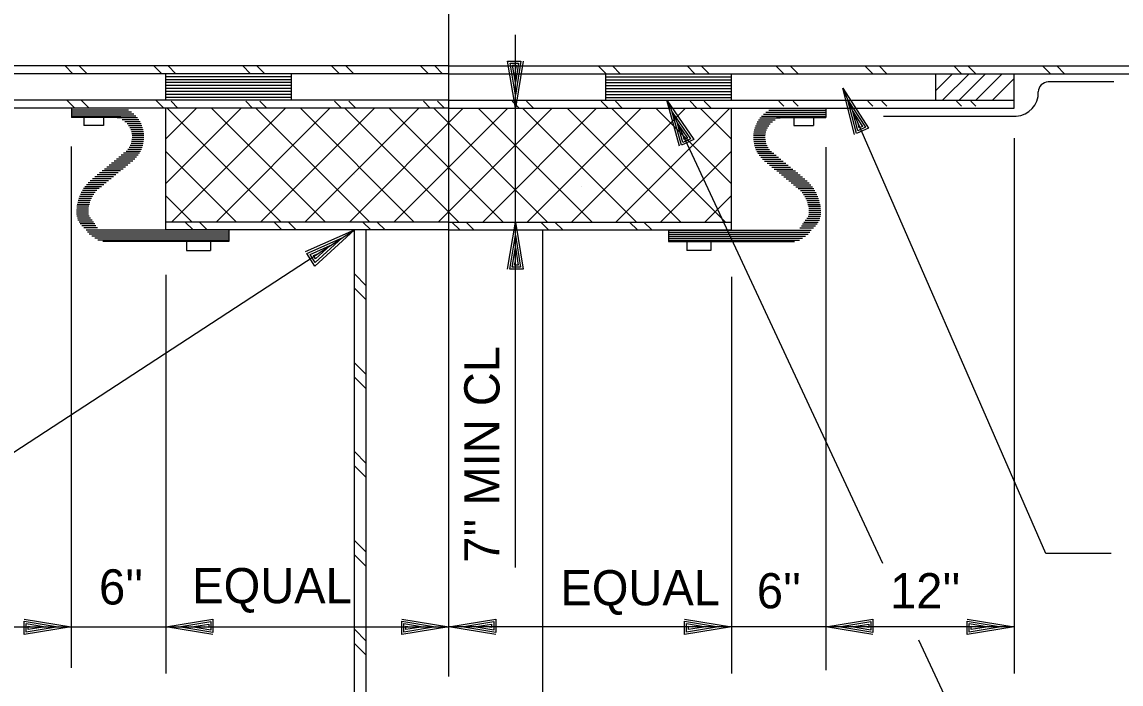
# Model space of a CAD drawing. Extents: x 22422.9 to 22498.9, y 22369.6 to 22415.
# Drawn here: x 22465.87 to 22471.7, y 22384.56 to 22388.07 of the extents above; entities that cross this region are included whole.
import ezdxf

# ---------------------------------------------------------------- set-up
doc = ezdxf.new("R2010")
doc.units = 0
for name, color, linetype in [('Level 1', 7, 'Continuous'), ('Level 10', 7, 'Continuous'), ('Level 2', 7, 'Continuous'), ('Level 4', 7, 'Continuous'), ('Level 7', 7, 'Continuous'), ('Level 8', 7, 'Continuous')]:
    doc.layers.add(name, color=color, linetype=linetype)

msp = doc.modelspace()

# ---------------------------------------------------------------- linework, layer by layer
at = {"layer": 'Level 1'}
for p, q in [((22468.1298, 22384.5979), (22468.1298, 22394.0328)), ((22468.4836, 22387.613), (22468.4836, 22388.0015)), ((22467.2965, 22387.7797), (22466.6298, 22387.7797)), ((22467.2965, 22387.764), (22466.6298, 22387.764)), ((22468.9631, 22387.7797), (22469.6298, 22387.7797)), ((22468.9631, 22387.764), (22469.6298, 22387.764)), ((22470.7131, 22387.7069), (22470.8015, 22387.7953)), ((22470.7493, 22387.6547), (22470.8899, 22387.7953)), ((22470.8377, 22387.6547), (22470.9783, 22387.7953)), ((22470.9261, 22387.6547), (22471.0667, 22387.7953)), ((22471.0145, 22387.6547), (22471.1298, 22387.77)), ((22467.2965, 22387.7484), (22466.6298, 22387.7484)), ((22467.2965, 22387.7328), (22466.6298, 22387.7328)), ((22467.2965, 22387.7172), (22466.6298, 22387.7172)), ((22467.2965, 22387.7015), (22466.6298, 22387.7015)), ((22468.9631, 22387.7484), (22469.6298, 22387.7484)), ((22468.9631, 22387.7328), (22469.6298, 22387.7328)), ((22468.9631, 22387.7172), (22469.6298, 22387.7172)), ((22468.9631, 22387.7015), (22469.6298, 22387.7015)), ((22468.1298, 22387.6547), (22465.1298, 22387.6547)), ((22467.2965, 22387.6859), (22466.6298, 22387.6859)), ((22467.2965, 22387.6703), (22466.6298, 22387.6703)), ((22468.1298, 22387.6547), (22471.1298, 22387.6547)), ((22468.9631, 22387.6859), (22469.6298, 22387.6859)), ((22468.9631, 22387.6703), (22469.6298, 22387.6703)), ((22468.1298, 22387.613), (22465.1298, 22387.613)), ((22466.6298, 22386.9672), (22466.6298, 22387.613)), ((22468.1298, 22387.613), (22471.1298, 22387.613)), ((22468.4836, 22387.0088), (22468.4836, 22387.613)), ((22469.6298, 22386.9672), (22469.6298, 22387.613)), ((22466.1946, 22387.5633), (22466.1946, 22387.5204)), ((22466.2982, 22387.5633), (22466.2982, 22387.5204)), ((22468.4836, 22387.5713), (22468.4836, 22387.5713)), ((22469.9614, 22387.5633), (22469.9614, 22387.5204)), ((22470.065, 22387.5633), (22470.065, 22387.5204)), ((22470.8989, 22387.5691), (22470.8989, 22387.5691)), ((22466.2982, 22387.5204), (22466.1946, 22387.5204)), ((22469.9614, 22387.5204), (22470.065, 22387.5204)), ((22466.1276, 22387.4098), (22466.1276, 22384.6433)), ((22470.1298, 22387.4065), (22470.1298, 22384.632)), ((22471.1298, 22387.4529), (22471.1298, 22384.6134)), ((22467.6298, 22387.2588), (22467.6298, 22387.2588)), ((22468.4836, 22387.252), (22468.4836, 22387.252)), ((22468.8041, 22387.2588), (22468.8041, 22387.2588)), ((22468.834, 22387.1962), (22468.834, 22387.1962)), ((22468.1298, 22387.0088), (22466.6298, 22387.0088)), ((22468.1298, 22387.0088), (22469.6298, 22387.0088)), ((22468.4836, 22385.1752), (22468.4836, 22387.0088)), ((22468.1298, 22386.9672), (22466.6298, 22386.9672)), ((22468.1298, 22386.9672), (22469.6298, 22386.9672)), ((22468.4836, 22386.9463), (22468.4836, 22386.9463)), ((22466.7386, 22386.9055), (22466.7386, 22386.8578)), ((22466.866, 22386.9055), (22466.866, 22386.8578)), ((22469.3936, 22386.9055), (22469.3936, 22386.8578)), ((22469.521, 22386.9055), (22469.521, 22386.8578)), ((22466.7386, 22386.8578), (22466.866, 22386.8578)), ((22469.521, 22386.8578), (22469.3936, 22386.8578)), ((22466.6298, 22386.7289), (22466.6298, 22384.6134)), ((22469.6298, 22386.7179), (22469.6298, 22384.6134)), ((22465.1298, 22384.8612), (22466.1276, 22384.8612)), ((22466.1276, 22384.8612), (22466.6298, 22384.8612)), ((22466.6298, 22384.8612), (22466.6298, 22384.8612)), ((22466.6298, 22384.8612), (22468.1298, 22384.8612)), ((22466.6991, 22384.8612), (22466.6991, 22384.8612)), ((22468.0605, 22384.8612), (22468.0605, 22384.8612)), ((22469.6298, 22384.8612), (22468.1298, 22384.8612)), ((22468.1298, 22384.8612), (22468.1298, 22384.8612)), ((22468.1298, 22384.8612), (22468.1298, 22384.8612)), ((22468.1991, 22384.8612), (22468.1991, 22384.8612)), ((22469.5605, 22384.8612), (22469.5605, 22384.8612)), ((22469.6298, 22384.8612), (22469.6298, 22384.8612)), ((22470.1298, 22384.8612), (22469.6298, 22384.8612)), ((22471.1298, 22384.8612), (22470.1298, 22384.8612))]:
    msp.add_line(p, q, dxfattribs=at)
at = {"layer": 'Level 10'}
for p, q in [((22464.6557, 22385.0258), (22467.6298, 22386.9672)), ((22467.6298, 22386.9672), (22467.6298, 22386.9672)), ((22467.5645, 22386.9245), (22467.5645, 22386.9245))]:
    msp.add_line(p, q, dxfattribs=at)
msp.add_lwpolyline([(22467.3695, 22386.8528), (22467.6298, 22386.9672), (22467.4203, 22386.7749), (22467.3769, 22386.8415), (22467.5645, 22386.9245), (22467.4222, 22386.794), (22467.3943, 22386.8367), (22467.5017, 22386.8835), (22467.424, 22386.8131), (22467.4126, 22386.8307), (22467.4364, 22386.8409)], dxfattribs=at)
at = {"layer": 'Level 2'}
for p, q in [((22468.1298, 22387.8369), (22461.434, 22387.8369)), ((22468.1298, 22387.8369), (22474.813, 22387.8369)), ((22468.1298, 22387.7953), (22461.4643, 22387.7953)), ((22466.6298, 22387.6547), (22466.6298, 22387.7953)), ((22467.2965, 22387.6547), (22467.2965, 22387.7953)), ((22468.1298, 22387.7953), (22474.7895, 22387.7953)), ((22468.9631, 22387.6547), (22468.9631, 22387.7953)), ((22469.6298, 22387.6547), (22469.6298, 22387.7953)), ((22470.7131, 22387.6547), (22470.7131, 22387.7953)), ((22471.1298, 22387.613), (22471.1298, 22387.7953)), ((22466.1285, 22387.613), (22466.1285, 22387.5633)), ((22470.1311, 22387.613), (22470.1311, 22387.5633)), ((22466.3909, 22387.5633), (22466.1285, 22387.5633)), ((22469.8687, 22387.5633), (22470.1311, 22387.5633)), ((22466.9643, 22386.9672), (22466.9643, 22386.9055)), ((22467.6298, 22383.8568), (22467.6298, 22386.9672)), ((22467.6923, 22383.8568), (22467.6923, 22386.9672)), ((22468.6298, 22383.8568), (22468.6298, 22386.9672)), ((22469.2953, 22386.9672), (22469.2953, 22386.9055)), ((22466.9643, 22386.9055), (22466.2958, 22386.9055)), ((22469.2953, 22386.9055), (22469.9648, 22386.9055))]:
    msp.add_line(p, q, dxfattribs=at)
for points in [[(22468.5249, 22387.8623), (22468.4836, 22387.613), (22468.4422, 22387.8623), (22468.5129, 22387.8623), (22468.4836, 22387.6823), (22468.4556, 22387.8517), (22468.5009, 22387.8517), (22468.4836, 22387.749), (22468.4689, 22387.841), (22468.4876, 22387.841), (22468.4836, 22387.8183)], [(22471.6445, 22385.2506), (22471.297, 22385.2506), (22470.2199, 22387.7191)], [(22470.2818, 22387.474), (22470.2199, 22387.7191), (22470.3575, 22387.5071), (22470.2928, 22387.4788), (22470.2477, 22387.6555), (22470.341, 22387.5115), (22470.2995, 22387.4934), (22470.2743, 22387.5944), (22470.3245, 22387.5159), (22470.3074, 22387.5085), (22470.302, 22387.5309)], [(22469.3548, 22387.4112), (22469.2868, 22387.6547), (22469.4297, 22387.4462), (22469.3657, 22387.4163), (22469.3161, 22387.5918), (22469.4131, 22387.4502), (22469.372, 22387.4311), (22469.3443, 22387.5314), (22469.3965, 22387.4543), (22469.3796, 22387.4464), (22469.3736, 22387.4686)], [(22470.4334, 22385.198), (22469.2868, 22387.6547)], [(22466.4724, 22387.613), (22466.1298, 22387.613)], [(22466.4118, 22387.613), (22466.1298, 22387.613)], [(22466.4323, 22387.6026), (22466.1298, 22387.6026)], [(22466.4476, 22387.5922), (22466.1298, 22387.5922)], [(22466.46, 22387.5817), (22466.1298, 22387.5817)], [(22469.7872, 22387.613), (22470.1298, 22387.613)], [(22469.7996, 22387.5817), (22470.1298, 22387.5817)], [(22469.812, 22387.5922), (22470.1298, 22387.5922)], [(22469.8274, 22387.6026), (22470.1298, 22387.6026)], [(22469.8478, 22387.613), (22470.1298, 22387.613)], [(22466.4703, 22387.5713), (22466.1298, 22387.5713)], [(22466.4789, 22387.5609), (22466.3708, 22387.5609)], [(22466.4863, 22387.5505), (22466.3975, 22387.5505)], [(22466.4926, 22387.5401), (22466.4128, 22387.5401)], [(22466.4978, 22387.5297), (22466.4237, 22387.5297)], [(22469.7618, 22387.5297), (22469.8359, 22387.5297)], [(22469.7671, 22387.5401), (22469.8468, 22387.5401)], [(22469.7733, 22387.5505), (22469.8621, 22387.5505)], [(22469.7807, 22387.5609), (22469.8888, 22387.5609)], [(22469.7893, 22387.5713), (22470.1298, 22387.5713)], [(22466.5023, 22387.5192), (22466.432, 22387.5192)], [(22466.5058, 22387.5088), (22466.4384, 22387.5088)], [(22466.5087, 22387.4984), (22466.4433, 22387.4984)], [(22466.5108, 22387.488), (22466.4469, 22387.488)], [(22466.5123, 22387.4776), (22466.4493, 22387.4776)], [(22466.5131, 22387.4672), (22466.4505, 22387.4672)], [(22469.7465, 22387.4672), (22469.8091, 22387.4672)], [(22469.7473, 22387.4776), (22469.8104, 22387.4776)], [(22469.7488, 22387.488), (22469.8127, 22387.488)], [(22469.7509, 22387.4984), (22469.8163, 22387.4984)], [(22469.7538, 22387.5088), (22469.8212, 22387.5088)], [(22469.7574, 22387.5192), (22469.8276, 22387.5192)], [(22466.504, 22387.4047), (22466.4352, 22387.4047)], [(22466.5072, 22387.4151), (22466.4408, 22387.4151)], [(22466.5098, 22387.4255), (22466.4451, 22387.4255)], [(22466.5116, 22387.4359), (22466.4481, 22387.4359)], [(22466.5128, 22387.4463), (22466.45, 22387.4463)], [(22466.5133, 22387.4567), (22466.4508, 22387.4567)], [(22469.7463, 22387.4567), (22469.8088, 22387.4567)], [(22469.7468, 22387.4463), (22469.8096, 22387.4463)], [(22469.748, 22387.4359), (22469.8115, 22387.4359)], [(22469.7498, 22387.4255), (22469.8145, 22387.4255)], [(22469.7524, 22387.4151), (22469.8188, 22387.4151)], [(22469.7556, 22387.4047), (22469.8244, 22387.4047)], [(22466.4744, 22387.3526), (22466.3803, 22387.3526)], [(22466.4825, 22387.363), (22466.393, 22387.363)], [(22466.4893, 22387.3734), (22466.4058, 22387.3734)], [(22466.4951, 22387.3838), (22466.4182, 22387.3838)], [(22466.5, 22387.3942), (22466.4278, 22387.3942)], [(22469.7597, 22387.3942), (22469.8318, 22387.3942)], [(22469.7645, 22387.3838), (22469.8414, 22387.3838)], [(22469.7703, 22387.3734), (22469.8538, 22387.3734)], [(22469.7772, 22387.363), (22469.8666, 22387.363)], [(22469.7852, 22387.3526), (22469.8793, 22387.3526)], [(22466.4025, 22387.2901), (22466.3037, 22387.2901)], [(22466.4153, 22387.3005), (22466.3165, 22387.3005)], [(22466.4281, 22387.3109), (22466.3292, 22387.3109)], [(22466.4408, 22387.3213), (22466.342, 22387.3213)], [(22466.4536, 22387.3317), (22466.3548, 22387.3317)], [(22466.4649, 22387.3422), (22466.3675, 22387.3422)], [(22469.7947, 22387.3422), (22469.8921, 22387.3422)], [(22469.806, 22387.3317), (22469.9049, 22387.3317)], [(22469.8188, 22387.3213), (22469.9176, 22387.3213)], [(22469.8315, 22387.3109), (22469.9304, 22387.3109)], [(22469.8443, 22387.3005), (22469.9432, 22387.3005)], [(22469.8571, 22387.2901), (22469.9559, 22387.2901)], [(22466.3387, 22387.238), (22466.2399, 22387.238)], [(22466.3515, 22387.2484), (22466.2526, 22387.2484)], [(22466.3642, 22387.2588), (22466.2654, 22387.2588)], [(22466.377, 22387.2692), (22466.2782, 22387.2692)], [(22466.3898, 22387.2797), (22466.2909, 22387.2797)], [(22469.8698, 22387.2797), (22469.9687, 22387.2797)], [(22469.8826, 22387.2692), (22469.9815, 22387.2692)], [(22469.8954, 22387.2588), (22469.9942, 22387.2588)], [(22469.9081, 22387.2484), (22470.007, 22387.2484)], [(22469.9209, 22387.238), (22470.0197, 22387.238)], [(22466.2643, 22387.1755), (22466.1868, 22387.1755)], [(22466.2751, 22387.1859), (22466.1932, 22387.1859)], [(22466.2877, 22387.1963), (22466.2004, 22387.1963)], [(22466.3004, 22387.2067), (22466.2085, 22387.2067)], [(22466.3132, 22387.2172), (22466.2176, 22387.2172)], [(22466.3259, 22387.2276), (22466.228, 22387.2276)], [(22469.9337, 22387.2276), (22470.0316, 22387.2276)], [(22469.9464, 22387.2172), (22470.042, 22387.2172)], [(22469.9592, 22387.2067), (22470.0511, 22387.2067)], [(22469.972, 22387.1963), (22470.0592, 22387.1963)], [(22469.9845, 22387.1859), (22470.0664, 22387.1859)], [(22469.9953, 22387.1755), (22470.0728, 22387.1755)], [(22466.2269, 22387.113), (22466.1621, 22387.113)], [(22466.2307, 22387.1234), (22466.1648, 22387.1234)], [(22466.2354, 22387.1338), (22466.168, 22387.1338)], [(22466.2409, 22387.1442), (22466.1718, 22387.1442)], [(22466.2475, 22387.1547), (22466.1761, 22387.1547)], [(22466.2552, 22387.1651), (22466.1811, 22387.1651)], [(22470.0044, 22387.1651), (22470.0785, 22387.1651)], [(22470.0121, 22387.1547), (22470.0835, 22387.1547)], [(22470.0187, 22387.1442), (22470.0878, 22387.1442)], [(22470.0242, 22387.1338), (22470.0916, 22387.1338)], [(22470.0289, 22387.1234), (22470.0949, 22387.1234)], [(22470.0327, 22387.113), (22470.0975, 22387.113)], [(22466.2185, 22387.0609), (22466.156, 22387.0609)], [(22466.2189, 22387.0713), (22466.1563, 22387.0713)], [(22466.2199, 22387.0817), (22466.157, 22387.0817)], [(22466.2215, 22387.0922), (22466.1582, 22387.0922)], [(22466.2239, 22387.1026), (22466.1599, 22387.1026)], [(22470.0357, 22387.1026), (22470.0997, 22387.1026)], [(22470.0381, 22387.0922), (22470.1014, 22387.0922)], [(22470.0398, 22387.0817), (22470.1026, 22387.0817)], [(22470.0407, 22387.0713), (22470.1033, 22387.0713)], [(22470.0411, 22387.0609), (22470.1036, 22387.0609)], [(22466.2189, 22387.0505), (22466.1563, 22387.0505)], [(22466.222, 22387.0401), (22466.157, 22387.0401)], [(22466.2292, 22387.0297), (22466.1608, 22387.0297)], [(22466.2389, 22387.0192), (22466.1634, 22387.0192)], [(22466.246, 22387.0088), (22466.1692, 22387.0088)], [(22466.2524, 22386.9984), (22466.1757, 22386.9984)], [(22468.4422, 22386.7595), (22468.4836, 22387.0088), (22468.5249, 22386.7595), (22468.4542, 22386.7595), (22468.4836, 22386.9395), (22468.5116, 22386.7702), (22468.4662, 22386.7702), (22468.4836, 22386.8728), (22468.4982, 22386.7808), (22468.4796, 22386.7808), (22468.4836, 22386.8035)], [(22470.0072, 22386.9984), (22470.084, 22386.9984)], [(22470.0137, 22387.0088), (22470.0904, 22387.0088)], [(22470.0207, 22387.0192), (22470.0962, 22387.0192)], [(22470.0304, 22387.0297), (22470.0988, 22387.0297)], [(22470.0376, 22387.0401), (22470.1026, 22387.0401)], [(22470.0407, 22387.0505), (22470.1033, 22387.0505)], [(22466.2582, 22386.988), (22466.1847, 22386.988)], [(22466.2672, 22386.9776), (22466.195, 22386.9776)], [(22466.9631, 22386.965), (22466.2073, 22386.965)], [(22466.9631, 22386.9545), (22466.2137, 22386.9545)], [(22466.9631, 22386.9441), (22466.2223, 22386.9441)], [(22469.2965, 22386.965), (22470.0524, 22386.965)], [(22469.2965, 22386.9545), (22470.0459, 22386.9545)], [(22469.2965, 22386.9441), (22470.0373, 22386.9441)], [(22469.9924, 22386.9776), (22470.0646, 22386.9776)], [(22470.0014, 22386.988), (22470.0749, 22386.988)], [(22466.9631, 22386.9337), (22466.2375, 22386.9337)], [(22466.9631, 22386.9233), (22466.2533, 22386.9233)], [(22466.9631, 22386.9129), (22466.2686, 22386.9129)], [(22469.2965, 22386.9337), (22470.0221, 22386.9337)], [(22469.2965, 22386.9233), (22470.0063, 22386.9233)], [(22469.2965, 22386.9129), (22469.991, 22386.9129)], [(22465.8782, 22384.9025), (22466.1276, 22384.8612), (22465.8782, 22384.8199), (22465.8782, 22384.8905), (22466.0582, 22384.8612), (22465.8889, 22384.8332), (22465.8889, 22384.8785), (22465.9916, 22384.8612), (22465.8996, 22384.8465), (22465.8996, 22384.8652), (22465.9222, 22384.8612)], [(22466.8791, 22384.8199), (22466.6298, 22384.8612), (22466.8791, 22384.9025), (22466.8791, 22384.8319), (22466.6991, 22384.8612), (22466.8685, 22384.8892), (22466.8685, 22384.8439), (22466.7658, 22384.8612), (22466.8578, 22384.8759), (22466.8578, 22384.8572), (22466.8351, 22384.8612)], [(22467.8805, 22384.9025), (22468.1298, 22384.8612), (22467.8805, 22384.8199), (22467.8805, 22384.8905), (22468.0605, 22384.8612), (22467.8911, 22384.8332), (22467.8911, 22384.8785), (22467.9938, 22384.8612), (22467.9018, 22384.8465), (22467.9018, 22384.8652), (22467.9245, 22384.8612)], [(22468.3791, 22384.8199), (22468.1298, 22384.8612), (22468.3791, 22384.9025), (22468.3791, 22384.8319), (22468.1991, 22384.8612), (22468.3685, 22384.8892), (22468.3685, 22384.8439), (22468.2658, 22384.8612), (22468.3578, 22384.8759), (22468.3578, 22384.8572), (22468.3351, 22384.8612)], [(22469.3805, 22384.9025), (22469.6298, 22384.8612), (22469.3805, 22384.8199), (22469.3805, 22384.8905), (22469.5605, 22384.8612), (22469.3911, 22384.8332), (22469.3911, 22384.8785), (22469.4938, 22384.8612), (22469.4018, 22384.8465), (22469.4018, 22384.8652), (22469.4245, 22384.8612)], [(22470.3791, 22384.8199), (22470.1298, 22384.8612), (22470.3791, 22384.9025), (22470.3791, 22384.8319), (22470.1991, 22384.8612), (22470.3685, 22384.8892), (22470.3685, 22384.8439), (22470.2658, 22384.8612), (22470.3578, 22384.8759), (22470.3578, 22384.8572), (22470.3351, 22384.8612)], [(22470.8805, 22384.9025), (22471.1298, 22384.8612), (22470.8805, 22384.8199), (22470.8805, 22384.8905), (22471.0605, 22384.8612), (22470.8911, 22384.8332), (22470.8911, 22384.8785), (22470.9938, 22384.8612), (22470.9018, 22384.8465), (22470.9018, 22384.8652), (22470.9245, 22384.8612)], [(22471.4047, 22383.8349), (22471.0696, 22383.8349), (22470.6237, 22384.7903)]]:
    msp.add_lwpolyline(points, dxfattribs=at)
at = {"layer": 'Level 7'}
for p, q in [((22471.3103, 22387.7536), (22471.6575, 22387.7536)), ((22470.4365, 22387.5713), (22471.1402, 22387.5713))]:
    msp.add_line(p, q, dxfattribs=at)
for centre, radius, start, end in [((22471.135, 22387.6937), 0.1225, 272.43665, 2.43665), ((22471.3103, 22387.6989), 0.0529, 90, 180)]:
    msp.add_arc(centre, radius, start, end, dxfattribs=at)
at = {"layer": 'Level 8'}
for p, q in [((22470.2199, 22387.7191), (22470.2199, 22387.7191)), ((22468.4836, 22387.6823), (22468.4836, 22387.6823)), ((22469.2868, 22387.6547), (22469.2868, 22387.6547)), ((22470.2477, 22387.6555), (22470.2477, 22387.6555)), ((22468.4836, 22387.613), (22468.4836, 22387.613)), ((22469.3161, 22387.5918), (22469.3161, 22387.5918)), ((22468.4836, 22387.0088), (22468.4836, 22387.0088)), ((22468.4836, 22386.9395), (22468.4836, 22386.9395)), ((22466.0582, 22384.8612), (22466.0582, 22384.8612)), ((22466.1276, 22384.8612), (22466.1276, 22384.8612)), ((22466.6298, 22384.8612), (22466.6298, 22384.8612)), ((22466.6991, 22384.8612), (22466.6991, 22384.8612)), ((22468.0605, 22384.8612), (22468.0605, 22384.8612)), ((22468.1298, 22384.8612), (22468.1298, 22384.8612)), ((22468.1298, 22384.8612), (22468.1298, 22384.8612)), ((22468.1991, 22384.8612), (22468.1991, 22384.8612)), ((22469.5605, 22384.8612), (22469.5605, 22384.8612)), ((22469.6298, 22384.8612), (22469.6298, 22384.8612)), ((22470.1298, 22384.8612), (22470.1298, 22384.8612)), ((22470.1991, 22384.8612), (22470.1991, 22384.8612)), ((22471.0605, 22384.8612), (22471.0605, 22384.8612)), ((22471.1298, 22384.8612), (22471.1298, 22384.8612))]:
    msp.add_line(p, q, dxfattribs=at)
for points in [[(22466.1364, 22387.7953), (22466.0947, 22387.8369)], [(22466.2118, 22387.7953), (22466.1702, 22387.8369)], [(22466.6078, 22387.7953), (22466.5662, 22387.8369)], [(22466.6832, 22387.7953), (22466.6416, 22387.8369)], [(22467.0792, 22387.7953), (22467.0376, 22387.8369)], [(22467.1546, 22387.7953), (22467.113, 22387.8369)], [(22467.5506, 22387.7953), (22467.509, 22387.8369)], [(22467.626, 22387.7953), (22467.5844, 22387.8369)], [(22468.022, 22387.7953), (22467.9804, 22387.8369)], [(22468.0975, 22387.7953), (22468.0558, 22387.8369)], [(22468.9648, 22387.7953), (22468.9232, 22387.8369)], [(22469.0403, 22387.7953), (22468.9986, 22387.8369)], [(22469.4362, 22387.7953), (22469.3946, 22387.8369)], [(22469.5117, 22387.7953), (22469.47, 22387.8369)], [(22469.9076, 22387.7953), (22469.866, 22387.8369)], [(22469.9831, 22387.7953), (22469.9414, 22387.8369)], [(22470.379, 22387.7953), (22470.3374, 22387.8369)], [(22470.4545, 22387.7953), (22470.4128, 22387.8369)], [(22470.8505, 22387.7953), (22470.8088, 22387.8369)], [(22470.9259, 22387.7953), (22470.8842, 22387.8369)], [(22471.3219, 22387.7953), (22471.2802, 22387.8369)], [(22471.3973, 22387.7953), (22471.3556, 22387.8369)], [(22466.1468, 22387.613), (22466.1052, 22387.6547)], [(22466.2223, 22387.613), (22466.1806, 22387.6547)], [(22466.6182, 22387.613), (22466.5766, 22387.6547)], [(22466.6937, 22387.613), (22466.6572, 22387.6494)], [(22467.0896, 22387.613), (22467.0532, 22387.6494)], [(22467.1651, 22387.613), (22467.1286, 22387.6494)], [(22467.561, 22387.613), (22467.5246, 22387.6494)], [(22467.6365, 22387.613), (22467.6, 22387.6494)], [(22468.0324, 22387.613), (22467.996, 22387.6494)], [(22468.1079, 22387.613), (22468.0714, 22387.6494)], [(22468.5038, 22387.613), (22468.4674, 22387.6494)], [(22468.5793, 22387.613), (22468.5428, 22387.6495)], [(22468.9752, 22387.613), (22468.9388, 22387.6494)], [(22469.0507, 22387.613), (22469.0142, 22387.6494)], [(22469.4467, 22387.613), (22469.4102, 22387.6494)], [(22469.5221, 22387.613), (22469.4856, 22387.6494)], [(22469.9076, 22387.6234), (22469.8816, 22387.6494)], [(22469.9831, 22387.6234), (22469.957, 22387.6494)], [(22470.379, 22387.6234), (22470.353, 22387.6494)], [(22470.4545, 22387.6234), (22470.4284, 22387.6495)], [(22470.8505, 22387.6234), (22470.8244, 22387.6495)], [(22470.9259, 22387.6234), (22470.8998, 22387.6495)], [(22466.6298, 22387.2141), (22467.0287, 22387.613)], [(22466.6298, 22387.4497), (22466.793, 22387.613)], [(22467.2405, 22387.0088), (22466.6363, 22387.613)], [(22466.6603, 22387.0088), (22467.2645, 22387.613)], [(22467.4762, 22387.0088), (22466.872, 22387.613)], [(22466.896, 22387.0088), (22467.5002, 22387.613)], [(22467.7119, 22387.0088), (22467.1077, 22387.613)], [(22467.1317, 22387.0088), (22467.7359, 22387.613)], [(22467.9476, 22387.0088), (22467.3434, 22387.613)], [(22467.3674, 22387.0088), (22467.9716, 22387.613)], [(22468.1833, 22387.0088), (22467.5791, 22387.613)], [(22467.6031, 22387.0088), (22468.2073, 22387.613)], [(22468.419, 22387.0088), (22467.8148, 22387.613)], [(22467.8388, 22387.0088), (22468.443, 22387.613)], [(22468.6547, 22387.0088), (22468.0505, 22387.613)], [(22468.0745, 22387.0088), (22468.6787, 22387.613)], [(22468.8904, 22387.0088), (22468.2862, 22387.613)], [(22468.3102, 22387.0088), (22468.9144, 22387.613)], [(22469.1261, 22387.0088), (22468.5219, 22387.613)], [(22468.5459, 22387.0088), (22469.1501, 22387.613)], [(22469.3618, 22387.0088), (22468.7576, 22387.613)], [(22468.7816, 22387.0088), (22469.3858, 22387.613)], [(22469.5975, 22387.0088), (22468.9933, 22387.613)], [(22469.0173, 22387.0088), (22469.6215, 22387.613)], [(22469.6298, 22387.2122), (22469.229, 22387.613)], [(22469.6298, 22387.4479), (22469.4647, 22387.613)], [(22467.0048, 22387.0088), (22466.6298, 22387.3838)], [(22469.253, 22387.0088), (22469.6298, 22387.3856)], [(22466.7691, 22387.0088), (22466.6298, 22387.1481)], [(22469.4887, 22387.0088), (22469.6298, 22387.1499)], [(22466.7742, 22386.9672), (22466.7325, 22387.0088)], [(22466.8496, 22386.9672), (22466.8079, 22387.0088)], [(22467.2456, 22386.9672), (22467.2039, 22387.0088)], [(22467.321, 22386.9672), (22467.2793, 22387.0088)], [(22467.717, 22386.9672), (22467.6753, 22387.0088)], [(22467.7924, 22386.9672), (22467.7507, 22387.0088)], [(22468.1884, 22386.9672), (22468.1467, 22387.0088)], [(22468.2638, 22386.9672), (22468.2221, 22387.0088)], [(22468.6598, 22386.9672), (22468.6181, 22387.0088)], [(22468.7352, 22386.9672), (22468.6935, 22387.0088)], [(22469.1312, 22386.9672), (22469.0895, 22387.0088)], [(22469.2066, 22386.9672), (22469.165, 22387.0088)], [(22467.6923, 22386.671), (22467.6298, 22386.7335)], [(22467.6923, 22386.5955), (22467.6298, 22386.658)], [(22467.6923, 22386.1996), (22467.6298, 22386.2621)], [(22467.6923, 22386.1241), (22467.6298, 22386.1866)], [(22467.6923, 22385.7282), (22467.6298, 22385.7907)], [(22467.6923, 22385.6527), (22467.6298, 22385.7152)], [(22467.6923, 22385.2568), (22467.6298, 22385.3193)], [(22467.6923, 22385.1813), (22467.6298, 22385.2438)], [(22467.6923, 22384.7854), (22467.6298, 22384.8479)], [(22467.6923, 22384.7099), (22467.6298, 22384.7724)]]:
    msp.add_lwpolyline(points, dxfattribs=at)

# ---------------------------------------------------------------- texts
at = {"layer": 'Level 4'}
msp.add_text("7'' MIN CL ", height=0.186667, rotation=90, dxfattribs=at).set_placement((22468.3993, 22385.2012))
for s, p in [("6''", (22466.2751, 22384.9795)), ('EQUAL', (22466.7696, 22384.9863)), ('EQUAL', (22468.7227, 22384.9751)), ("6''", (22469.7646, 22384.9593)), ("12''", (22470.4712, 22384.9592))]:
    msp.add_text(s, height=0.18667, dxfattribs=at).set_placement(p)

doc.saveas('drawing.dxf')
